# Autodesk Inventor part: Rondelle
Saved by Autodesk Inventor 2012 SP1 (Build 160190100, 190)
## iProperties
Created: 2014-12
Part Number: Rondelle
Material: Default
Document SubType Name: Modeling
Designer: Bruno
Density: 1 g/cm^3
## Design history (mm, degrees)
node "Rondelle1"
node "Rondelle"
node "Base1"
